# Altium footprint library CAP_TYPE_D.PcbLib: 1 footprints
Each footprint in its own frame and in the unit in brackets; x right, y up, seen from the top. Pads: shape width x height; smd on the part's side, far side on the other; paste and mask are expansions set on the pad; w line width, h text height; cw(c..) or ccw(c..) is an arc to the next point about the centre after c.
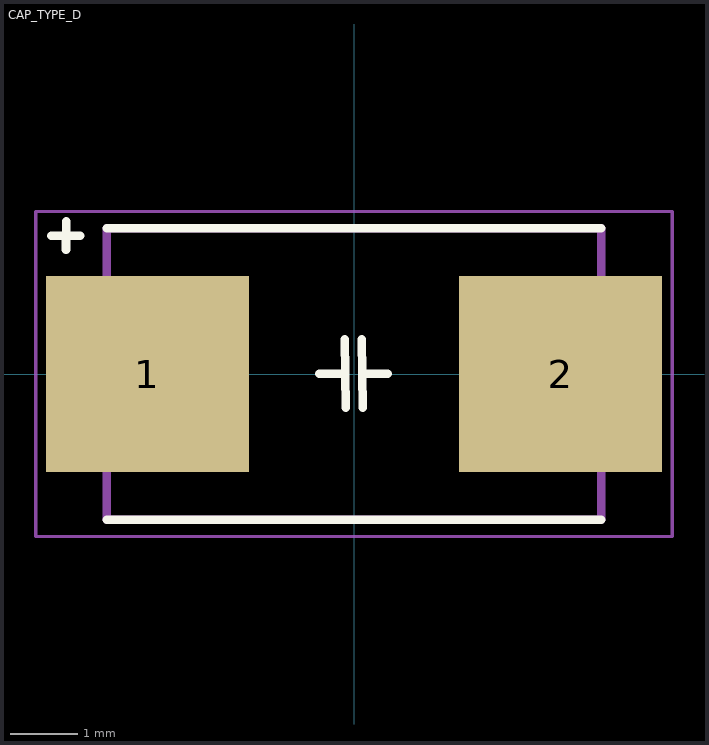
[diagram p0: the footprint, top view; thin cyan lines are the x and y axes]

## CAP_TYPE_D [mm]
pads (2):
  rect 3x2.9 smd: 1(-3.05,0) 2(3.05,0)
Top Overlay:
  lines w0.127: -4.472,2.042 -4.045,2.04 ; -4.253,1.836 -4.252,2.253 ; -3.65,-2.15 3.65,-2.15 ; -3.65,2.15 3.65,2.15 ; -0.515,0.001 -0.127,0 ; -0.134,0.516 -0.12,-0.5 ; 0.113,0.516 0.128,-0.5 ; 0.146,0.004 0.501,0.004
Mechanical 13:
  lines w0.127: -3.65,-2.15 -3.65,2.15 3.65,2.15 3.65,-2.15 -3.65,-2.15
Mechanical 15:
  lines w0.05: -4.699,-2.4 4.699,-2.4 4.699,2.4 -4.699,2.4 -4.699,-2.4
3D body "CAP_TYPE_D.STEP": height 3.1, standoff 0, extent -3.683,-2.141 3.617,2.159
